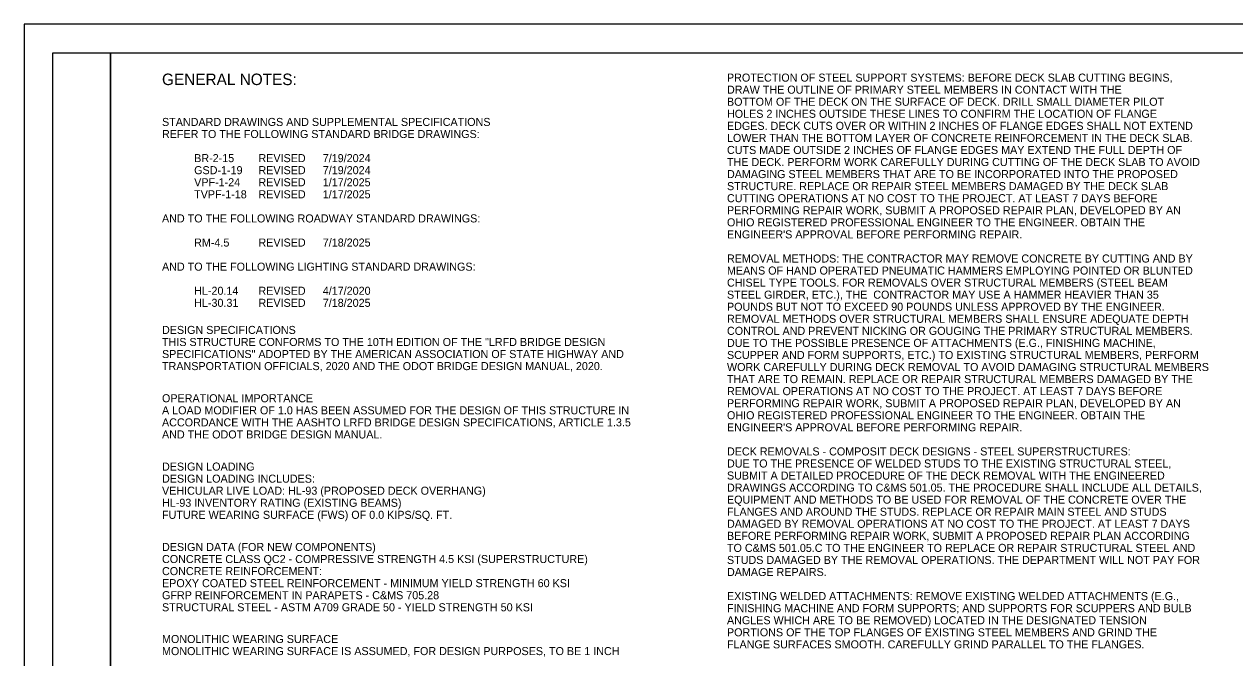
# Model space of a CAD drawing. Extents: x 0 to 34, y 0 to 22.
# Drawn here: x 0 to 21.08, y 10.97 to 22 of the extents above; entities that cross this region are included whole.
import ezdxf

# ---------------------------------------------------------------- set-up
doc = ezdxf.new("R2010")
doc.units = 0
for name, color, linetype in [('SH_Border', 7, 'Continuous'), ('SH_Cut_Line', 7, 'Continuous'), ('SH_Text', 7, 'Continuous')]:
    doc.layers.add(name, color=color, linetype=linetype)

msp = doc.modelspace()

# ---------------------------------------------------------------- linework, layer by layer
at = {"layer": 'SH_Border'}
for points in [[(0.5, 21.5), (1.5, 21.5), (1.5, 0.5), (0.5, 0.5)], [(1.5, 21.5), (33.5, 21.5), (33.5, 0.5), (1.5, 0.5)]]:
    msp.add_lwpolyline(points, close=True, dxfattribs=at)
at = {"layer": 'SH_Cut_Line'}
msp.add_lwpolyline([(0, 0), (34, 0), (34, 22), (0, 22)], close=True, dxfattribs=at)
at = {"layer": 'SH_Text'}
msp.add_lwpolyline([(3.167, 19.744), (3.167, 19.744), (3.167, 19.744), (3.167, 19.744)], close=True, dxfattribs=at)

# ---------------------------------------------------------------- texts
for s, height, p in [('GENERAL NOTES:', 0.2, (2.4, 20.94)), ('PROTECTION OF STEEL SUPPORT SYSTEMS: BEFORE DECK SLAB CUTTING BEGINS, ', 0.14, (12.24, 21)), ('DRAW THE OUTLINE OF PRIMARY STEEL MEMBERS IN CONTACT WITH THE ', 0.14, (12.24, 20.79)), ('BOTTOM OF THE DECK ON THE SURFACE OF DECK. DRILL SMALL DIAMETER PILOT ', 0.14, (12.24, 20.58)), ('HOLES 2 INCHES OUTSIDE THESE LINES TO CONFIRM THE LOCATION OF FLANGE ', 0.14, (12.24, 20.37)), ('STANDARD DRAWINGS AND SUPPLEMENTAL SPECIFICATIONS', 0.14, (2.4, 20.228)), ('EDGES. DECK CUTS OVER OR WITHIN 2 INCHES OF FLANGE EDGES SHALL NOT EXTEND ', 0.14, (12.24, 20.16)), ('REFER TO THE FOLLOWING STANDARD BRIDGE DRAWINGS:', 0.14, (2.4, 20.018)), ('LOWER THAN THE BOTTOM LAYER OF CONCRETE REINFORCEMENT IN THE DECK SLAB. ', 0.14, (12.24, 19.95)), ('CUTS MADE OUTSIDE 2 INCHES OF FLANGE EDGES MAY EXTEND THE FULL DEPTH OF ', 0.14, (12.24, 19.74)), ('BR-2-15', 0.14, (2.96, 19.598)), ('REVISED', 0.14, (4.08, 19.598)), ('7/19/2024', 0.14, (5.2, 19.598)), ('THE DECK. PERFORM WORK CAREFULLY DURING CUTTING OF THE DECK SLAB TO AVOID ', 0.14, (12.24, 19.53)), ('GSD-1-19', 0.14, (2.96, 19.388)), ('REVISED', 0.14, (4.08, 19.388)), ('7/19/2024', 0.14, (5.2, 19.388)), ('DAMAGING STEEL MEMBERS THAT ARE TO BE INCORPORATED INTO THE PROPOSED ', 0.14, (12.24, 19.32)), ('VPF-1-24', 0.14, (2.96, 19.178)), ('REVISED', 0.14, (4.08, 19.178)), ('1/17/2025', 0.14, (5.2, 19.178)), ('STRUCTURE. REPLACE OR REPAIR STEEL MEMBERS DAMAGED BY THE DECK SLAB ', 0.14, (12.24, 19.11)), ('TVPF-1-18', 0.14, (2.96, 18.968)), ('REVISED', 0.14, (4.08, 18.968)), ('1/17/2025', 0.14, (5.2, 18.968)), ('CUTTING OPERATIONS AT NO COST TO THE PROJECT. AT LEAST 7 DAYS BEFORE ', 0.14, (12.24, 18.9)), ('PERFORMING REPAIR WORK, SUBMIT A PROPOSED REPAIR PLAN, DEVELOPED BY AN ', 0.14, (12.24, 18.69)), ('AND TO THE FOLLOWING ROADWAY STANDARD DRAWINGS:', 0.14, (2.4, 18.548)), ('OHIO REGISTERED PROFESSIONAL ENGINEER TO THE ENGINEER. OBTAIN THE ', 0.14, (12.24, 18.48)), ("ENGINEER'S APPROVAL BEFORE PERFORMING REPAIR.", 0.14, (12.24, 18.27)), ('RM-4.5', 0.14, (2.96, 18.128)), ('REVISED', 0.14, (4.08, 18.128)), ('7/18/2025', 0.14, (5.2, 18.128)), ('REMOVAL METHODS: THE CONTRACTOR MAY REMOVE CONCRETE BY CUTTING AND BY ', 0.14, (12.24, 17.85)), ('AND TO THE FOLLOWING LIGHTING STANDARD DRAWINGS:', 0.14, (2.4, 17.708)), ('MEANS OF HAND OPERATED PNEUMATIC HAMMERS EMPLOYING POINTED OR BLUNTED ', 0.14, (12.24, 17.64)), ('CHISEL TYPE TOOLS. FOR REMOVALS OVER STRUCTURAL MEMBERS (STEEL BEAM ', 0.14, (12.24, 17.43)), ('HL-20.14', 0.14, (2.96, 17.288)), ('REVISED', 0.14, (4.08, 17.288)), ('4/17/2020', 0.14, (5.2, 17.288)), ('STEEL GIRDER, ETC.), THE  CONTRACTOR MAY USE A HAMMER HEAVIER THAN 35 ', 0.14, (12.24, 17.22)), ('HL-30.31', 0.14, (2.96, 17.078)), ('REVISED', 0.14, (4.08, 17.078)), ('7/18/2025', 0.14, (5.2, 17.078)), ('POUNDS BUT NOT TO EXCEED 90 POUNDS UNLESS APPROVED BY THE ENGINEER. ', 0.14, (12.24, 17.01)), ('REMOVAL METHODS OVER STRUCTURAL MEMBERS SHALL ENSURE ADEQUATE DEPTH ', 0.14, (12.24, 16.8)), ('DESIGN SPECIFICATIONS', 0.14, (2.4, 16.606)), ('CONTROL AND PREVENT NICKING OR GOUGING THE PRIMARY STRUCTURAL MEMBERS. ', 0.14, (12.24, 16.59)), ('THIS STRUCTURE CONFORMS TO THE 10TH EDITION OF THE "LRFD BRIDGE DESIGN ', 0.14, (2.4, 16.396)), ('DUE TO THE POSSIBLE PRESENCE OF ATTACHMENTS (E.G., FINISHING MACHINE, ', 0.14, (12.24, 16.38)), ('SPECIFICATIONS" ADOPTED BY THE AMERICAN ASSOCIATION OF STATE HIGHWAY AND ', 0.14, (2.4, 16.186)), ('SCUPPER AND FORM SUPPORTS, ETC.) TO EXISTING STRUCTURAL MEMBERS, PERFORM ', 0.14, (12.24, 16.17)), ('TRANSPORTATION OFFICIALS, 2020 AND THE ODOT BRIDGE DESIGN MANUAL, 2020.', 0.14, (2.4, 15.976)), ('WORK CAREFULLY DURING DECK REMOVAL TO AVOID DAMAGING STRUCTURAL MEMBERS ', 0.14, (12.24, 15.96)), ('THAT ARE TO REMAIN. REPLACE OR REPAIR STRUCTURAL MEMBERS DAMAGED BY THE ', 0.14, (12.24, 15.75)), ('REMOVAL OPERATIONS AT NO COST TO THE PROJECT. AT LEAST 7 DAYS BEFORE ', 0.14, (12.24, 15.54)), ('OPERATIONAL IMPORTANCE', 0.14, (2.4, 15.416)), ('PERFORMING REPAIR WORK, SUBMIT A PROPOSED REPAIR PLAN, DEVELOPED BY AN ', 0.14, (12.24, 15.33)), ('A LOAD MODIFIER OF 1.0 HAS BEEN ASSUMED FOR THE DESIGN OF THIS STRUCTURE IN ', 0.14, (2.4, 15.206)), ('OHIO REGISTERED PROFESSIONAL ENGINEER TO THE ENGINEER. OBTAIN THE ', 0.14, (12.24, 15.12)), ('ACCORDANCE WITH THE AASHTO LRFD BRIDGE DESIGN SPECIFICATIONS, ARTICLE 1.3.5 ', 0.14, (2.4, 14.996)), ("ENGINEER'S APPROVAL BEFORE PERFORMING REPAIR.", 0.14, (12.24, 14.91)), ('AND THE ODOT BRIDGE DESIGN MANUAL.', 0.14, (2.4, 14.786)), ('DECK REMOVALS - COMPOSIT DECK DESIGNS - STEEL SUPERSTRUCTURES:', 0.14, (12.24, 14.49)), ('DESIGN LOADING ', 0.14, (2.4, 14.226)), ('DUE TO THE PRESENCE OF WELDED STUDS TO THE EXISTING STRUCTURAL STEEL, ', 0.14, (12.24, 14.28)), ('DESIGN LOADING INCLUDES:', 0.14, (2.4, 14.016)), ('SUBMIT A DETAILED PROCEDURE OF THE DECK REMOVAL WITH THE ENGINEERED ', 0.14, (12.24, 14.07)), ('VEHICULAR LIVE LOAD: HL-93 (PROPOSED DECK OVERHANG)', 0.14, (2.4, 13.806)), ('DRAWINGS ACCORDING TO C&MS 501.05. THE PROCEDURE SHALL INCLUDE ALL DETAILS, ', 0.14, (12.24, 13.86)), ('HL-93 INVENTORY RATING (EXISTING BEAMS)', 0.14, (2.4, 13.596)), ('EQUIPMENT AND METHODS TO BE USED FOR REMOVAL OF THE CONCRETE OVER THE ', 0.14, (12.24, 13.65)), ('FUTURE WEARING SURFACE (FWS) OF 0.0 KIPS/SQ. FT.', 0.14, (2.4, 13.386)), ('FLANGES AND AROUND THE STUDS. REPLACE OR REPAIR MAIN STEEL AND STUDS ', 0.14, (12.24, 13.44)), ('DAMAGED BY REMOVAL OPERATIONS AT NO COST TO THE PROJECT. AT LEAST 7 DAYS ', 0.14, (12.24, 13.23)), ('BEFORE PERFORMING REPAIR WORK, SUBMIT A PROPOSED REPAIR PLAN ACCORDING ', 0.14, (12.24, 13.02)), ('DESIGN DATA (FOR NEW COMPONENTS)', 0.14, (2.4, 12.826)), ('TO C&MS 501.05.C TO THE ENGINEER TO REPLACE OR REPAIR STRUCTURAL STEEL AND ', 0.14, (12.24, 12.81)), ('CONCRETE CLASS QC2 - COMPRESSIVE STRENGTH 4.5 KSI (SUPERSTRUCTURE)', 0.14, (2.4, 12.616)), ('STUDS DAMAGED BY THE REMOVAL OPERATIONS. THE DEPARTMENT WILL NOT PAY FOR ', 0.14, (12.24, 12.6)), ('CONCRETE REINFORCEMENT:', 0.14, (2.4, 12.406)), ('DAMAGE REPAIRS.  ', 0.14, (12.24, 12.39)), ('EPOXY COATED STEEL REINFORCEMENT - MINIMUM YIELD STRENGTH 60 KSI', 0.14, (2.4, 12.196)), ('GFRP REINFORCEMENT IN PARAPETS - C&MS 705.28', 0.14, (2.4, 11.986)), ('EXISTING WELDED ATTACHMENTS: REMOVE EXISTING WELDED ATTACHMENTS (E.G.,', 0.14, (12.24, 11.97)), ('STRUCTURAL STEEL - ASTM A709 GRADE 50 - YIELD STRENGTH 50 KSI', 0.14, (2.4, 11.776)), ('FINISHING MACHINE AND FORM SUPPORTS; AND SUPPORTS FOR SCUPPERS AND BULB', 0.14, (12.24, 11.76)), ('ANGLES WHICH ARE TO BE REMOVED) LOCATED IN THE DESIGNATED TENSION ', 0.14, (12.24, 11.55)), ('PORTIONS OF THE TOP FLANGES OF EXISTING STEEL MEMBERS AND GRIND THE ', 0.14, (12.24, 11.34)), ('MONOLITHIC WEARING SURFACE', 0.14, (2.4, 11.223)), ('FLANGE SURFACES SMOOTH. CAREFULLY GRIND PARALLEL TO THE FLANGES.', 0.14, (12.24, 11.13)), ('MONOLITHIC WEARING SURFACE IS ASSUMED, FOR DESIGN PURPOSES, TO BE 1 INCH ', 0.14, (2.4, 11.013))]:
    msp.add_text(s, height=height, dxfattribs=at).set_placement(p)

doc.saveas('drawing.dxf')
